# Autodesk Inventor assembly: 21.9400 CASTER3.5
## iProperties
Created: 2010-10
Part Number: 21.9400 CASTER3.5
Document SubType Name: Assembly
Designer: Administrator
Translation Standard: STEP AP214IS
FileName: Colson-2.03256.445 BRK5 .step.step
PreProcessor: SolidWorks 2010
PostProcessor: Build: 236a, Release: 2009 RTM - Date: Fri 02/22/2008
Sent Units: Inches
Uncertainty: 1e-05
Author: Administrator
